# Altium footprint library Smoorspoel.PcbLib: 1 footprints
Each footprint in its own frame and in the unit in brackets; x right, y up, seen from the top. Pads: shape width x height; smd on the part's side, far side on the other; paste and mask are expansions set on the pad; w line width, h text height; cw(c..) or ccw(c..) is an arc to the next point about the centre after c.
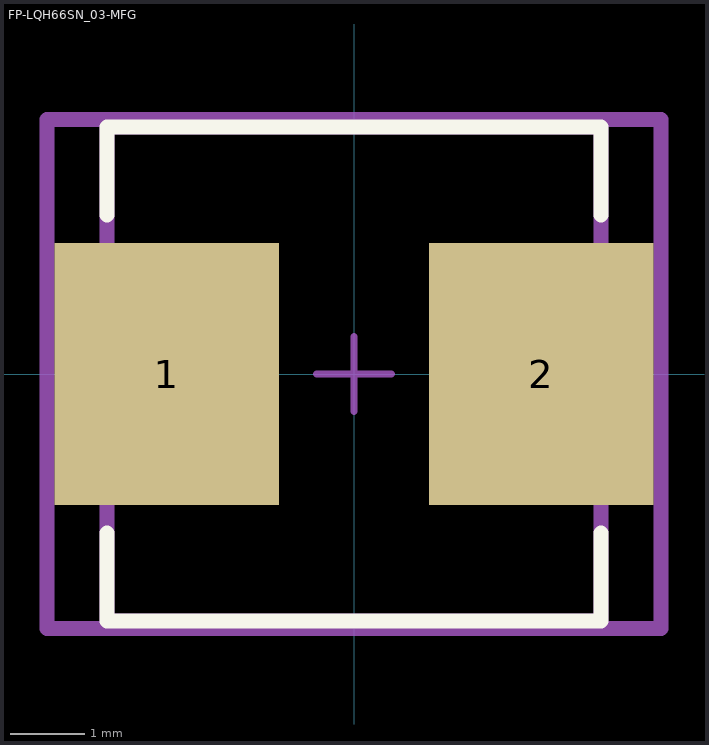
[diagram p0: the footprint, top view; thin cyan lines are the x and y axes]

## FP-LQH66SN_03-MFG [mm]
pads (2):
  rect 3x3.5 smd paste+0 mask+0: 1(-2.5,0) 2(2.5,0)
Top Overlay:
  lines w0.2: -3.3,-2.125 -3.3,-3.3 3.3,-3.3 3.3,-2.125 ; -3.3,2.125 -3.3,3.3 3.3,3.3 3.3,2.125
Top Assembly:
  lines w0.2: -4.1,-3.4 -4.1,3.4 4.1,3.4 4.1,-3.4 -4.1,-3.4
  text ".Designator" at 0,0.188 h1
Top 3D Body:
  lines w0.2: -3.3,-3.3 -3.3,3.3 3.3,3.3 3.3,-3.3 -3.3,-3.3
Top Courtyard:
  lines w0.2: -4.1,-3.4 -4.1,3.4 4.1,3.4 4.1,-3.4 -4.1,-3.4
Top Component Center:
  lines w0.1: -0.5,0 0.5,0 ; 0,-0.5 0,0.5
3D body "Ind_Murata_LQH66SN100M03L_eec.STEP": height 0.25, standoff 0, extent -4.1,-3.4 4.1,3.4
